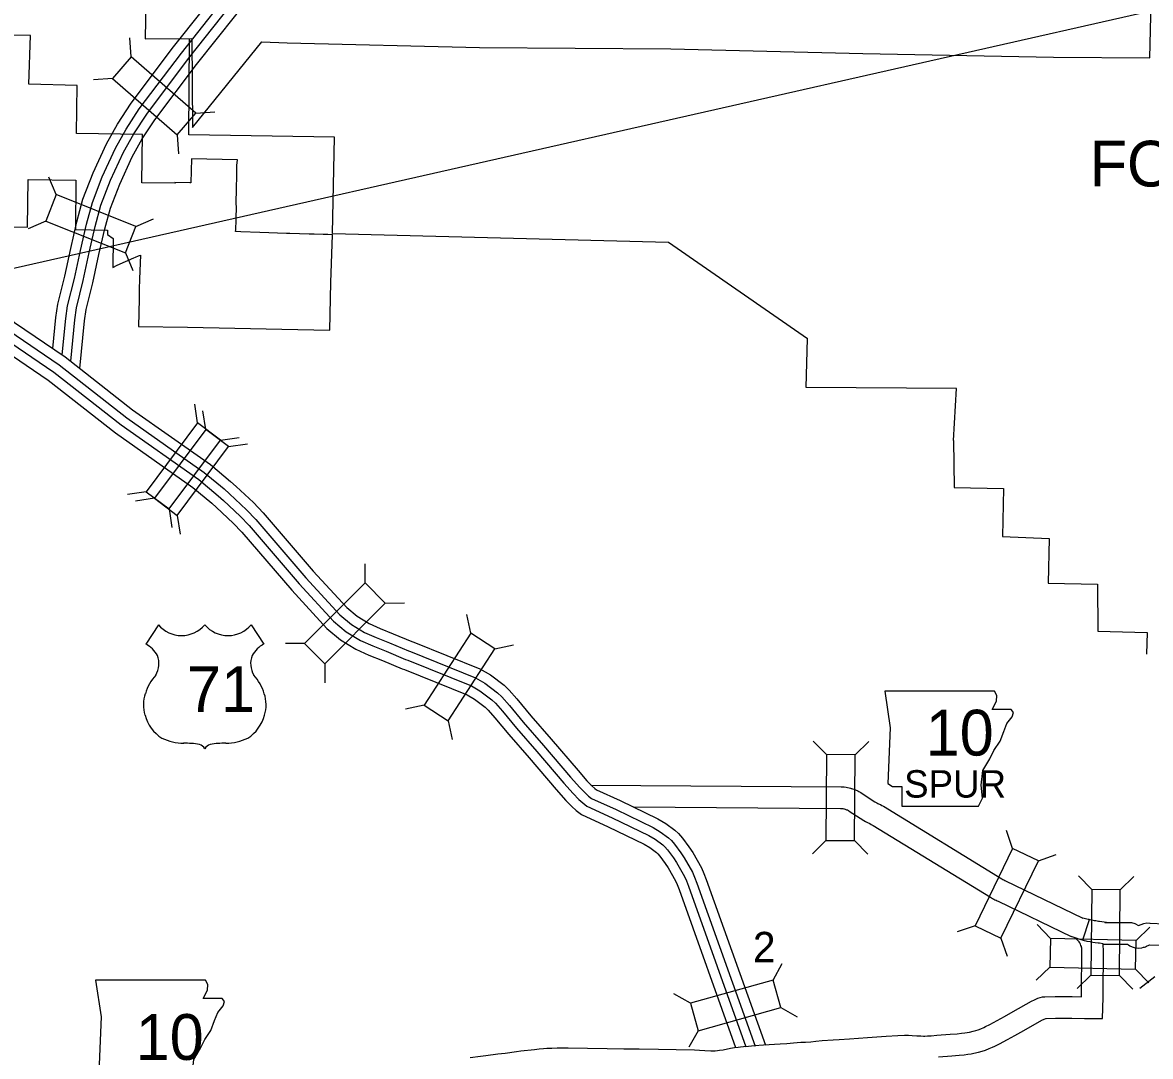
# Model space of a CAD drawing. Extents: x 1370567 to 1373900, y 377514 to 379648.
# Drawn here: x 1370881.3 to 1371037.6, y 379160.9 to 379304.1 of the extents above; entities that cross this region are included whole.
import ezdxf

# ---------------------------------------------------------------- set-up
doc = ezdxf.new("R2010")
doc.units = 0
doc.layers.add('Default', color=7, linetype='Continuous')
doc.layers.add('Survey Names', color=7, linetype='Continuous')

msp = doc.modelspace()

# ---------------------------------------------------------------- linework, layer by layer
at = {"layer": 'Default'}
for p, q in [((1370896.39, 379299.37), (1370896.21, 379302)), ((1370893.79, 379296.38), (1370891.16, 379296.19)), ((1370905.36, 379291.58), (1370907.99, 379291.76)), ((1370902.76, 379288.59), (1370902.95, 379285.95)), ((1370886.01, 379280.3), (1370884.97, 379282.72)), ((1370884.55, 379276.62), (1370882.12, 379275.57)), ((1370897.05, 379275.9), (1370899.47, 379276.94)), ((1370895.58, 379272.22), (1370896.63, 379269.79)), ((1370905.58, 379248.66), (1370905.2, 379251.27)), ((1370906.71, 379247.75), (1370906.33, 379250.36)), ((1370908.75, 379246.29), (1370911.36, 379246.67)), ((1370909.88, 379245.38), (1370912.49, 379245.76)), ((1370898.47, 379239.14), (1370895.86, 379238.76)), ((1370899.6, 379238.23), (1370896.99, 379237.85)), ((1370901.64, 379236.77), (1370902.02, 379234.16)), ((1370902.77, 379235.86), (1370903.15, 379233.24)), ((1370928.8, 379226.52), (1370928.79, 379229.16)), ((1370931.6, 379223.72), (1370934.24, 379223.73)), ((1370943.46, 379219.53), (1370942.9, 379222.11)), ((1370900.15, 379220.71), (1370898.42, 379218.03)), ((1370913.02, 379220.71), (1370914.75, 379218.03)), ((1370920.41, 379218.11), (1370917.77, 379218.11)), ((1370946.78, 379217.37), (1370949.36, 379217.93)), ((1370923.21, 379215.31), (1370923.21, 379212.67)), ((1370937, 379209.55), (1370934.42, 379209)), ((1370940.33, 379207.4), (1370940.88, 379204.82)), ((1370992.75, 379202.71), (1370990.9, 379204.59)), ((1370996.71, 379202.69), (1370998.59, 379204.54)), ((1371018.53, 379189.72), (1371017.67, 379192.21)), ((1370992.67, 379190.83), (1370990.79, 379188.98)), ((1370996.63, 379190.81), (1370998.48, 379188.93)), ((1371022.1, 379187.99), (1371024.59, 379188.86)), ((1371029.5, 379184.03), (1371027.66, 379185.92)), ((1371033.46, 379183.99), (1371035.35, 379185.84)), ((1371013.36, 379179.02), (1371010.87, 379178.16)), ((1371023.79, 379177.25), (1371021.96, 379179.16)), ((1371035.66, 379176.97), (1371037.57, 379178.79)), ((1371016.92, 379177.3), (1371017.79, 379174.81)), ((1370985.33, 379171.49), (1370986.62, 379173.79)), ((1371023.69, 379173.29), (1371021.78, 379171.47)), ((1371029.38, 379172.15), (1371027.49, 379170.31)), ((1371033.34, 379172.11), (1371035.18, 379170.22)), ((1371035.57, 379173.01), (1371037.39, 379171.1)), ((1371038.23, 379171.95), (1371036.16, 379170.31)), ((1370973.89, 379168.28), (1370971.59, 379169.57)), ((1370986.4, 379167.67), (1370988.7, 379166.38)), ((1370974.96, 379164.47), (1370973.66, 379162.17)), ((1371012.56, 379164.29), (1371012.56, 379164.29)), ((1371013.18, 379161.36), (1371013.18, 379161.36))]:
    msp.add_line(p, q, dxfattribs=at)
for points in [[(1370885.53, 379258.97), (1370885.95, 379263.29), (1370886.23, 379265.14), (1370887.18, 379268.98), (1370888, 379272.84), (1370888.84, 379276.51), (1370889.7, 379279.65), (1370891.11, 379283.32), (1370892.98, 379287.35), (1370894.49, 379290.06), (1370896.38, 379292.97), (1370902.27, 379300.75), (1370910.46, 379311.11), (1370916.74, 379318.94), (1370926.87, 379331.81), (1370940.04, 379348.43), (1370946.53, 379356.49), (1370949.77, 379359.68), (1370952.66, 379362.08), (1370956.27, 379364.68), (1370963.87, 379369.63), (1370980.13, 379380.02)], [(1370886.83, 379258.12), (1370887.32, 379263.12), (1370887.58, 379264.88), (1370888.52, 379268.67), (1370889.34, 379272.54), (1370890.17, 379276.18), (1370891.01, 379279.22), (1370892.37, 379282.78), (1370894.2, 379286.73), (1370895.67, 379289.35), (1370897.5, 379292.18), (1370903.36, 379299.91), (1370911.53, 379310.26), (1370917.82, 379318.08), (1370927.95, 379330.96), (1370941.11, 379347.57), (1370947.55, 379355.56), (1370950.69, 379358.66), (1370953.51, 379361), (1370957.05, 379363.55), (1370964.61, 379368.47), (1370980.87, 379378.87)], [(1370888, 379257.21), (1370888.56, 379262.97), (1370888.81, 379264.63), (1370889.73, 379268.39), (1370890.56, 379272.27), (1370891.38, 379275.87), (1370892.2, 379278.83), (1370893.53, 379282.3), (1370895.32, 379286.16), (1370896.74, 379288.71), (1370898.53, 379291.46), (1370904.35, 379299.14), (1370912.51, 379309.48), (1370918.8, 379317.31), (1370928.93, 379330.18), (1370942.09, 379346.79), (1370948.48, 379354.72), (1370951.53, 379357.73), (1370954.27, 379360.01), (1370957.76, 379362.52), (1370965.29, 379367.42), (1370981.55, 379377.81)], [(1370889.29, 379256.2), (1370889.92, 379262.8), (1370890.16, 379264.36), (1370891.07, 379268.08), (1370891.9, 379271.98), (1370892.72, 379275.54), (1370893.51, 379278.4), (1370894.79, 379281.76), (1370896.54, 379285.53), (1370897.92, 379288), (1370899.65, 379290.67), (1370905.44, 379298.3), (1370913.59, 379308.62), (1370919.87, 379316.45), (1370930.01, 379329.33), (1370943.16, 379345.93), (1370949.5, 379353.8), (1370952.46, 379356.71), (1370955.11, 379358.92), (1370958.53, 379361.38), (1370966.03, 379366.27), (1370982.29, 379376.65)], [(1370876.23, 379315.65), (1370889.22, 379315.49), (1370889.21, 379315.22), (1370898.56, 379315.1), (1370898.31, 379301.89), (1370904.78, 379301.93), (1370904.88, 379289.59), (1370914.47, 379301.48), (1370918.02, 379301.34), (1370944.64, 379300.66), (1370971.18, 379300.49), (1370997.78, 379299.84), (1371024.18, 379299.35), (1371037.53, 379299.24), (1371038.47, 379337.82)], [(1370888.72, 379282.28), (1370888.65, 379275.44), (1370893.03, 379275.37), (1370893.03, 379275.37), (1370893.08, 379275.37), (1370893.08, 379274.77), (1370893.9, 379274.21), (1370893.84, 379270.21), (1370894.46, 379270.5), (1370895.6, 379271.01), (1370896.77, 379271.54), (1370896.98, 379271.64), (1370897.41, 379271.82), (1370897.66, 379271.91), (1370897.54, 379268.64), (1370897.51, 379267.16), (1370897.48, 379265.87), (1370897.39, 379262.04), (1370904.18, 379261.91), (1370910.73, 379261.78), (1370917.27, 379261.65), (1370923.9, 379261.53), (1370924.07, 379268.14), (1370924.28, 379274.74), (1370924.19, 379274.74), (1370923.63, 379274.76), (1370922.98, 379274.76), (1370921.76, 379274.8), (1370921.06, 379274.82), (1370918.39, 379274.91), (1370917.89, 379274.93), (1370914.2, 379275.05), (1370911.56, 379275.14), (1370910.86, 379275.18), (1370910.87, 379275.42), (1370910.88, 379275.57), (1370910.93, 379276.67), (1370910.94, 379277.33), (1370910.96, 379278.28), (1370910.93, 379279.32), (1370910.94, 379279.84), (1370910.96, 379280.36), (1370910.96, 379280.44), (1370910.98, 379281.65), (1370911.01, 379282.4), (1370911.03, 379283.48), (1370911.03, 379284.33), (1370911.12, 379285.11), (1370904.76, 379285.26), (1370904.64, 379281.93), (1370904.5, 379281.93), (1370902.43, 379281.97), (1370902.47, 379281.86), (1370897.84, 379281.94), (1370897.93, 379288.6), (1370888.82, 379288.77), (1370888.81, 379288.77), (1370888.9, 379295.39), (1370882.22, 379295.61), (1370882.42, 379302.32), (1370875.91, 379302.43)], [(1370924.26, 379274.89), (1370924.55, 379288.25), (1370904.38, 379288.56), (1370904.46, 379301.79)], [(1370856.14, 379299.26), (1370863.52, 379287.01), (1370864.07, 379286.19), (1370865.46, 379283.7), (1370871.21, 379273.32), (1370872.91, 379270.34), (1370873.14, 379269.88), (1370873.78, 379268.95), (1370875.17, 379267.19), (1370875.91, 379266.33), (1370877.4, 379264.96), (1370879.42, 379263.21), (1370880.22, 379262.59), (1370887.22, 379257.82), (1370896.57, 379250.49)], [(1370852.66, 379297.29), (1370860.18, 379284.82), (1370860.65, 379284.11), (1370861.97, 379281.75), (1370867.72, 379271.37), (1370869.39, 379268.43), (1370869.7, 379267.83), (1370870.56, 379266.58), (1370872.09, 379264.63), (1370873.04, 379263.54), (1370874.74, 379261.98), (1370876.88, 379260.12), (1370877.86, 379259.36), (1370884.86, 379254.59), (1370894.19, 379247.28)], [(1370857.01, 379292.73), (1370861.33, 379285.58), (1370861.82, 379284.82), (1370863.17, 379282.42), (1370868.92, 379272.04), (1370870.6, 379269.09), (1370870.88, 379268.53), (1370871.67, 379267.4), (1370873.15, 379265.51), (1370874.03, 379264.5), (1370875.65, 379263), (1370877.75, 379261.18), (1370878.67, 379260.47), (1370885.67, 379255.7), (1370895.01, 379248.38)], [(1370858.1, 379293.35), (1370862.37, 379286.26), (1370862.89, 379285.47), (1370864.26, 379283.03), (1370870.01, 379272.65), (1370871.7, 379269.68), (1370871.96, 379269.18), (1370872.67, 379268.14), (1370874.11, 379266.31), (1370874.93, 379265.37), (1370876.49, 379263.94), (1370878.55, 379262.15), (1370879.41, 379261.48), (1370886.41, 379256.71), (1370895.76, 379249.39)], [(1370875.4, 379275.9), (1370882.01, 379275.77), (1370882.11, 379282.4), (1370888.72, 379282.28)], [(1370924.26, 379274.89), (1370970.86, 379273.72)], [(1370970.86, 379273.72), (1370990.09, 379260.36)], [(1371010.36, 379246.22), (1371010.78, 379253.42), (1370989.92, 379253.56), (1370990.09, 379260.36)], [(1370896.57, 379250.49), (1370907.36, 379242.92), (1370910.17, 379240.56), (1370910.94, 379239.88), (1370913.35, 379237.62), (1370914.69, 379236.2), (1370921.62, 379228.13), (1370926.26, 379223.09), (1370927.72, 379221.88), (1370929.37, 379220.87), (1370930.87, 379220.19), (1370932.7, 379219.47), (1370935.28, 379218.38), (1370935.56, 379218.3), (1370944.7, 379214.6), (1370946.16, 379213.75), (1370948.07, 379212.33), (1370948.75, 379211.66), (1370949.84, 379210.44), (1370951.77, 379208.1), (1370954.58, 379204.86), (1370958.32, 379200.5), (1370959.54, 379199.1), (1370960.24, 379198.41), (1370960.66, 379198.02), (1370960.89, 379197.83), (1370964.17, 379196.35), (1370969.37, 379193.84), (1370970.47, 379193.19), (1370971.71, 379192.25), (1370972.24, 379191.79), (1370972.78, 379191.15), (1370973.67, 379189.93), (1370974.2, 379189.14), (1370975.4, 379187.03), (1370975.74, 379186.27), (1370976.07, 379185.42), (1370984.27, 379162.45)], [(1370895.01, 379248.38), (1370905.76, 379240.83), (1370908.46, 379238.57), (1370909.16, 379237.94), (1370911.5, 379235.76), (1370912.75, 379234.44), (1370919.66, 379226.39), (1370924.44, 379221.19), (1370926.19, 379219.74), (1370928.15, 379218.54), (1370929.85, 379217.78), (1370931.71, 379217.04), (1370934.42, 379215.89), (1370934.71, 379215.81), (1370943.54, 379212.23), (1370944.71, 379211.55), (1370946.36, 379210.32), (1370946.85, 379209.84), (1370947.84, 379208.73), (1370949.77, 379206.4), (1370952.6, 379203.15), (1370956.34, 379198.78), (1370957.63, 379197.31), (1370958.42, 379196.51), (1370958.96, 379196.02), (1370959.51, 379195.58), (1370963.06, 379193.97), (1370968.12, 379191.53), (1370969, 379191), (1370970.05, 379190.22), (1370970.35, 379189.95), (1370970.71, 379189.52), (1370971.53, 379188.41), (1370971.97, 379187.76), (1370973.05, 379185.85), (1370973.32, 379185.25), (1370973.62, 379184.5), (1370981.55, 379162.24)], [(1370895.76, 379249.39), (1370906.52, 379241.82), (1370909.27, 379239.52), (1370910.01, 379238.86), (1370912.38, 379236.65), (1370913.67, 379235.28), (1370920.59, 379227.22), (1370925.31, 379222.1), (1370926.91, 379220.76), (1370928.73, 379219.65), (1370930.34, 379218.93), (1370932.18, 379218.19), (1370934.83, 379217.08), (1370935.11, 379217), (1370944.09, 379213.36), (1370945.4, 379212.6), (1370947.17, 379211.28), (1370947.76, 379210.71), (1370948.79, 379209.54), (1370950.72, 379207.21), (1370953.54, 379203.96), (1370957.28, 379199.59), (1370958.54, 379198.16), (1370959.29, 379197.41), (1370959.77, 379196.97), (1370960.17, 379196.65), (1370963.59, 379195.11), (1370968.71, 379192.63), (1370969.7, 379192.04), (1370970.84, 379191.19), (1370971.25, 379190.83), (1370971.7, 379190.3), (1370972.55, 379189.13), (1370973.03, 379188.42), (1370974.17, 379186.41), (1370974.47, 379185.74), (1370974.79, 379184.93), (1370982.84, 379162.34)], [(1370894.19, 379247.28), (1370904.92, 379239.74), (1370907.56, 379237.54), (1370908.23, 379236.93), (1370910.53, 379234.78), (1370911.73, 379233.52), (1370918.63, 379225.48), (1370923.49, 379220.19), (1370925.38, 379218.62), (1370927.5, 379217.32), (1370929.31, 379216.51), (1370931.19, 379215.76), (1370933.96, 379214.59), (1370934.27, 379214.51), (1370942.94, 379211), (1370943.95, 379210.41), (1370945.46, 379209.28), (1370945.86, 379208.89), (1370946.8, 379207.83), (1370948.72, 379205.51), (1370951.55, 379202.25), (1370955.3, 379197.87), (1370956.62, 379196.37), (1370957.47, 379195.51), (1370958.07, 379194.97), (1370958.79, 379194.4), (1370962.48, 379192.73), (1370967.47, 379190.31), (1370968.24, 379189.86), (1370969.18, 379189.15), (1370969.36, 379188.99), (1370969.63, 379188.67), (1370970.4, 379187.62), (1370970.8, 379187.03), (1370971.82, 379185.23), (1370972.05, 379184.72), (1370972.33, 379184.02), (1370980.13, 379162.14)], [(1371010.36, 379246.22), (1371010.44, 379239.73), (1371017.25, 379239.58), (1371017.13, 379232.93), (1371023.6, 379232.67), (1371023.46, 379226.46), (1371030.3, 379226.31), (1371030.35, 379219.84), (1371037.19, 379219.65), (1371037.11, 379216.65)], [(1370960.07, 379198.5), (1370994.78, 379198.26), (1370995.21, 379198.24), (1370995.47, 379198.2), (1370996.06, 379198.06), (1370996.16, 379198.03), (1370996.2, 379198.02), (1370996.34, 379197.99), (1370996.54, 379197.92), (1370996.78, 379197.84), (1370997.07, 379197.7), (1370997.24, 379197.6), (1370997.48, 379197.48), (1370997.68, 379197.32), (1370999.46, 379196.18), (1370999.64, 379196.07), (1370999.72, 379196.03), (1370999.85, 379195.96), (1370999.97, 379195.9), (1371000.22, 379195.79), (1371000.42, 379195.65), (1371000.62, 379195.56), (1371017.06, 379185.5), (1371017.17, 379185.43), (1371017.3, 379185.37), (1371017.33, 379185.35), (1371017.47, 379185.3), (1371028.25, 379180.08)], [(1370966.02, 379195.46), (1370994.7, 379195.26), (1370994.91, 379195.25), (1370995.01, 379195.23), (1370995.15, 379195.2), (1370995.17, 379195.2), (1370995.33, 379195.14), (1370995.53, 379195.09), (1370995.61, 379195.07), (1370995.67, 379195.05), (1370995.79, 379194.97), (1370995.81, 379194.97), (1370995.9, 379194.89), (1370997.9, 379193.61), (1370998.16, 379193.46), (1370998.32, 379193.37), (1370998.51, 379193.28), (1370998.65, 379193.2), (1370998.74, 379193.16), (1370998.94, 379193.03), (1370999.21, 379192.91), (1371015.45, 379182.97), (1371015.74, 379182.78), (1371015.91, 379182.71), (1371015.94, 379182.69), (1371016.09, 379182.61), (1371016.24, 379182.56), (1371016.41, 379182.47), (1371016.51, 379182.43), (1371026.67, 379177.52)], [(1371031.56, 379179.46), (1371030.9, 379179.57), (1371030.57, 379179.58), (1371030.43, 379179.59), (1371030.24, 379179.64), (1371030.05, 379179.67), (1371029.89, 379179.7), (1371029.55, 379179.78), (1371029.26, 379179.84), (1371029.13, 379179.86), (1371029.02, 379179.89), (1371028.25, 379180.08)], [(1371028.26, 379177.05), (1371029.21, 379179.87)], [(1371031.33, 379179.48), (1371034.76, 379179.44), (1371035.02, 379179.45), (1371035.48, 379179.34), (1371035.99, 379179.06), (1371036.73, 379179.34), (1371037.15, 379179.42), (1371037.53, 379179.38), (1371037.61, 379179.37), (1371039.57, 379179.29), (1371041.11, 379179.11), (1371041.43, 379179.06), (1371041.71, 379179), (1371041.86, 379178.97), (1371041.98, 379178.94), (1371042.09, 379178.92), (1371042.57, 379178.8)], [(1371012.56, 379164.29), (1371013.06, 379164.4), (1371013.46, 379164.52), (1371013.75, 379164.6), (1371014.11, 379164.75), (1371014.54, 379164.93), (1371014.79, 379165.05), (1371015.36, 379165.33), (1371016.41, 379165.89), (1371017.4, 379166.44), (1371018.63, 379167.12), (1371021.16, 379168.55), (1371021.57, 379168.76), (1371022.03, 379168.98), (1371022.34, 379169.09), (1371022.68, 379169.15), (1371023.01, 379169.18), (1371024.44, 379169.21), (1371026.78, 379169.19), (1371028.07, 379169.17), (1371028.09, 379171.3), (1371028.12, 379173.88), (1371028.13, 379175.4), (1371028.13, 379175.65), (1371028.11, 379175.92), (1371028.1, 379176.02), (1371028.07, 379176.12), (1371028.01, 379176.27), (1371027.93, 379176.45), (1371027.88, 379176.57), (1371027.84, 379176.64), (1371027.76, 379176.76), (1371027.68, 379176.87), (1371027.58, 379176.97), (1371027.42, 379177.11), (1371027.27, 379177.23), (1371027.16, 379177.33)], [(1371013.18, 379161.36), (1371013.8, 379161.49), (1371014.3, 379161.64), (1371014.76, 379161.77), (1371015.28, 379161.99), (1371015.77, 379162.2), (1371016.09, 379162.35), (1371016.72, 379162.65), (1371017.84, 379163.26), (1371018.85, 379163.81), (1371020.09, 379164.5), (1371022.58, 379165.91), (1371022.89, 379166.07), (1371023.13, 379166.18), (1371023.18, 379166.18), (1371024.46, 379166.21), (1371026.75, 379166.19), (1371028.5, 379166.16), (1371031.01, 379166.16), (1371031.07, 379169.07), (1371031.09, 379171.26), (1371031.12, 379173.85), (1371031.13, 379175.41), (1371031.13, 379175.78), (1371031.1, 379176.13), (1371031.09, 379176.36), (1371031.07, 379176.49)], [(1371031.07, 379176.5), (1371030.59, 379176.58), (1371030.41, 379176.59), (1371029.98, 379176.62), (1371029.66, 379176.69), (1371029.49, 379176.72), (1371029.27, 379176.77), (1371028.88, 379176.85), (1371028.75, 379176.88), (1371028.52, 379176.91), (1371028.23, 379177), (1371028.02, 379177.05), (1371027.72, 379177.14), (1371027.47, 379177.25), (1371026.67, 379177.52)], [(1371031.1, 379176.48), (1371034.47, 379176.45), (1371034.51, 379176.42), (1371034.58, 379176.37), (1371034.76, 379176.25), (1371035.1, 379176.07), (1371035.53, 379175.94), (1371036, 379175.9), (1371036.44, 379175.94), (1371036.69, 379176.03), (1371036.81, 379176.06), (1371036.94, 379176.11), (1371037.11, 379176.17), (1371037.43, 379176.31), (1371037.52, 379176.37), (1371039.34, 379176.3), (1371040.68, 379176.14), (1371040.88, 379176.1), (1371041.08, 379176.07), (1371041.17, 379176.05), (1371041.37, 379176), (1371041.46, 379175.98), (1371041.86, 379175.89)], [(1370964.64, 379161.96), (1370966.8, 379161.94), (1370969.47, 379161.89), (1370971.9, 379161.85), (1370974.46, 379161.81), (1370975.14, 379161.78), (1370975.88, 379161.75), (1370976.72, 379161.69), (1370976.97, 379161.67), (1370977.12, 379161.67), (1370977.31, 379161.69), (1370977.63, 379161.72), (1370977.93, 379161.76), (1370978.42, 379161.84), (1370979.46, 379162.04), (1370979.98, 379162.12), (1370980.51, 379162.19), (1370980.82, 379162.23), (1370981.25, 379162.28), (1370981.92, 379162.33), (1370982.75, 379162.4), (1370983.99, 379162.49), (1370986.3, 379162.65), (1370987.26, 379162.71), (1370988.15, 379162.78), (1370989.19, 379162.86), (1370989.84, 379162.9), (1370990.58, 379162.95), (1370991.27, 379163.01), (1370992.15, 379163.09), (1370993.68, 379163.2), (1370994.5, 379163.25), (1370995.95, 379163.36), (1370998.43, 379163.54), (1371001.01, 379163.71), (1371002.63, 379163.82), (1371003.56, 379163.86), (1371004.11, 379163.86), (1371004.62, 379163.82), (1371005.24, 379163.78), (1371005.83, 379163.75), (1371006.2, 379163.72), (1371006.38, 379163.72), (1371006.75, 379163.74), (1371007.27, 379163.77), (1371008.05, 379163.83), (1371009.89, 379163.97), (1371010.85, 379164.05), (1371011.45, 379164.12), (1371011.9, 379164.17), (1371012.25, 379164.23), (1371012.56, 379164.29)], [(1370943.34, 379160.74), (1370944.78, 379160.94), (1370945.53, 379161.03), (1370947.21, 379161.25), (1370948.19, 379161.38), (1370949.76, 379161.58), (1370950.4, 379161.66), (1370952.27, 379161.88), (1370952.91, 379161.95), (1370953.54, 379162.01), (1370954, 379162.03), (1370954.68, 379162.06), (1370955.42, 379162.08), (1370956.95, 379162.08), (1370959.63, 379162.04), (1370962.34, 379161.99), (1370964.64, 379161.96)], [(1371008.28, 379160.84), (1371010.12, 379160.98), (1371011.15, 379161.07), (1371011.81, 379161.14), (1371012.31, 379161.2), (1371012.78, 379161.27), (1371013.18, 379161.36)]]:
    msp.add_lwpolyline(points, dxfattribs=at)
for points in [[(1370905.36, 379291.58), (1370896.39, 379299.37), (1370893.79, 379296.38), (1370902.76, 379288.59)], [(1370897.05, 379275.9), (1370886.01, 379280.3), (1370884.55, 379276.62), (1370895.58, 379272.22)], [(1370905.58, 379248.66), (1370898.47, 379239.14), (1370901.64, 379236.77), (1370908.75, 379246.29)], [(1370906.71, 379247.75), (1370899.6, 379238.23), (1370902.77, 379235.86), (1370909.88, 379245.38)], [(1370928.8, 379226.52), (1370920.41, 379218.11), (1370923.21, 379215.31), (1370931.6, 379223.72)], [(1370940.33, 379207.4), (1370946.78, 379217.37), (1370943.46, 379219.53), (1370937, 379209.55)], [(1371000.81, 379211.5), (1371001.57, 379206.42), (1371001.23, 379198.72), (1371001.91, 379198.3), (1371003.17, 379198.3), (1371003.17, 379195.59), (1371013.83, 379195.59), (1371014.34, 379196.69), (1371014.17, 379198.47), (1371014.43, 379200.5), (1371015.36, 379202.11), (1371015.95, 379203.29), (1371016.79, 379204.56), (1371017.3, 379205.91), (1371017.72, 379207.01), (1371018.49, 379207.94), (1371018.65, 379208.54), (1371018.32, 379208.96), (1371015.69, 379208.96), (1371016.29, 379210.14), (1371016.37, 379210.9), (1371016.02, 379211.49)], [(1370992.75, 379202.71), (1370992.67, 379190.83), (1370996.63, 379190.81), (1370996.71, 379202.69)], [(1371016.92, 379177.3), (1371022.1, 379187.99), (1371018.53, 379189.72), (1371013.36, 379179.02)], [(1371033.34, 379172.11), (1371033.46, 379183.99), (1371029.5, 379184.03), (1371029.38, 379172.15)], [(1371035.66, 379176.97), (1371023.79, 379177.25), (1371023.69, 379173.29), (1371035.57, 379173.01)], [(1370891.46, 379171.46), (1370892.22, 379166.38), (1370891.88, 379158.68), (1370892.56, 379158.26), (1370893.82, 379158.26), (1370893.82, 379155.55), (1370904.48, 379155.55), (1370904.99, 379156.65), (1370904.82, 379158.43), (1370905.07, 379160.46), (1370906.01, 379162.07), (1370906.6, 379163.25), (1370907.44, 379164.52), (1370907.95, 379165.87), (1370908.37, 379166.97), (1370909.14, 379167.9), (1370909.3, 379168.5), (1370908.97, 379168.92), (1370906.34, 379168.92), (1370906.94, 379170.1), (1370907.02, 379170.86), (1370906.67, 379171.45)], [(1370985.33, 379171.49), (1370973.89, 379168.28), (1370974.96, 379164.47), (1370986.4, 379167.67)]]:
    msp.add_lwpolyline(points, close=True, dxfattribs=at)
for centre, radius, start, end in [((1370903.37, 379223.42), 4.21, 220.075, 319.6701), ((1370909.8, 379223.42), 4.21, 220.3299, 319.925), ((1370896.16, 379214.15), 4.5, 30.7809, 59.9883), ((1370917.01, 379214.15), 4.5, 120.0117, 149.2191), ((1370897.15, 379215.33), 3.08, 328.8105, 21.2108), ((1370916.02, 379215.33), 3.08, 158.7892, 211.1895), ((1370905.21, 379209.02), 7.19, 138.9565, 162.6913), ((1370907.96, 379209.02), 7.19, 17.3087, 41.0435), ((1370902.83, 379209.61), 4.75, 160.9576, 197.3819), ((1370910.33, 379209.61), 4.75, 342.6181, 19.0424), ((1370903.61, 379209.62), 5.5, 195.1074, 237.1312), ((1370909.56, 379209.62), 5.5, 302.8688, 344.8926), ((1370903.71, 379211.35), 7.06, 244.0771, 269.5779), ((1370909.46, 379211.35), 7.06, 270.4221, 295.9229), ((1370903.87, 379191.36), 12.93, 81.1942, 90.9539), ((1370905.49, 379202.95), 1.24, 28.0342, 72.9864), ((1370907.68, 379202.95), 1.24, 107.0136, 151.9658), ((1370909.3, 379191.36), 12.93, 89.0461, 98.8058)]:
    msp.add_arc(centre, radius, start, end, dxfattribs=at)
at = {"layer": 'Survey Names'}
msp.add_line((1371498.51, 379409.91), (1370792.1, 379250.17), dxfattribs=at)

# ---------------------------------------------------------------- texts
at = {"layer": 'Default'}
for s, height, p in [('FORT', 6.336, (1371029.22, 379281.42)), ('71', 6.336, (1370904.12, 379208.61)), ('10', 6.336, (1371006.49, 379202.59)), ('SPUR', 3.802, (1371003.5, 379196.76)), ('2', 4.22, (1370982.54, 379173.94)), ('10', 6.336, (1370897.01, 379160.43))]:
    msp.add_text(s, height=height, dxfattribs=at).set_placement(p)

doc.saveas('drawing.dxf')
